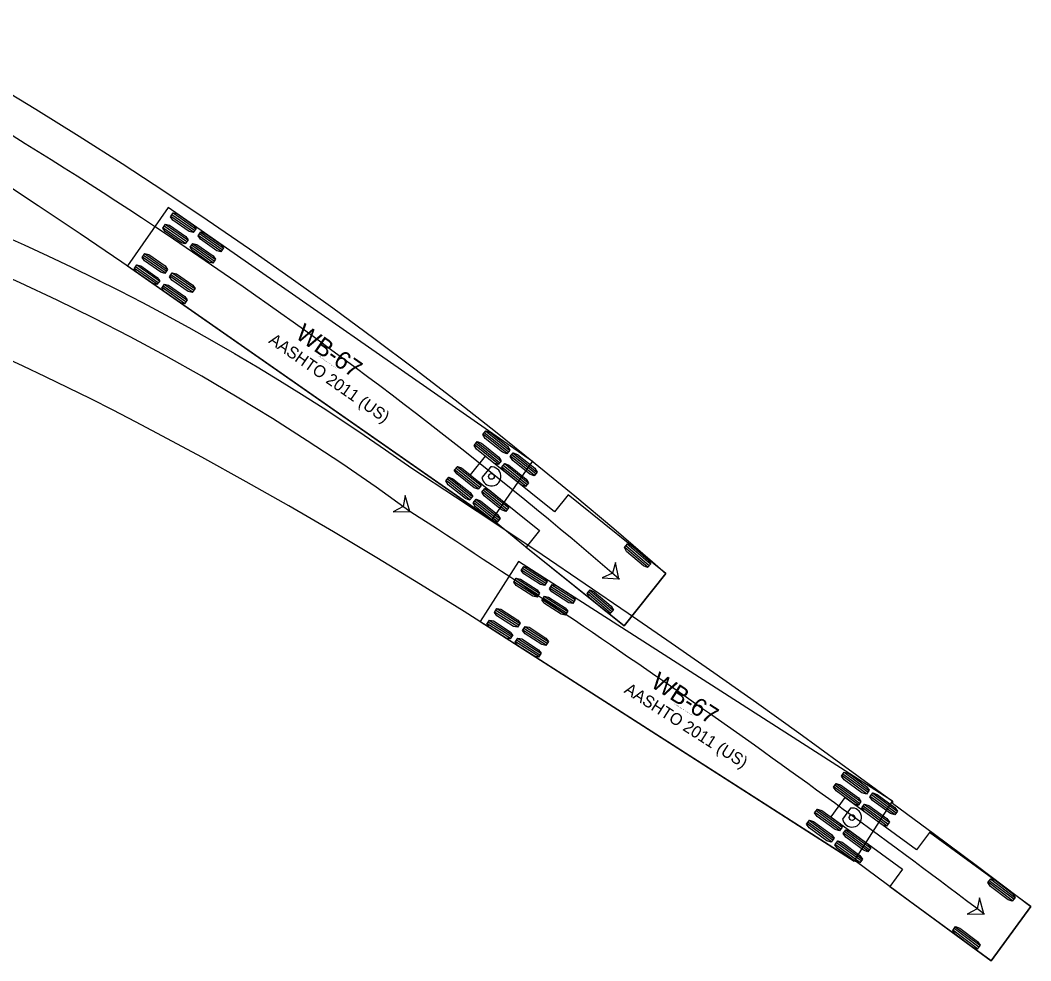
# Model space of a CAD drawing. Extents: x 2175591 to 2194071, y 76570 to 86955.
# Drawn here: x 2176719.9 to 2176840.5, y 77107.8 to 77220.1 of the extents above; entities that cross this region are included whole.
import ezdxf

# ---------------------------------------------------------------- set-up
doc = ezdxf.new("R2010")
doc.units = 0
doc.layers.add('C-UTIL-STRM-TEXT', color=7, linetype='Continuous')

msp = doc.modelspace()

# ---------------------------------------------------------------- linework, layer by layer
at = {"layer": 'C-UTIL-STRM-TEXT'}
for p, q in [((2176737.57, 77197.72), (2176732.71, 77190.75)), ((2176781.04, 77167.4), (2176737.57, 77197.72)), ((2176740.58, 77194.79), (2176737.87, 77196.67)), ((2176740.71, 77194.97), (2176738.01, 77196.86)), ((2176740.84, 77195.16), (2176738.14, 77197.05)), ((2176739.64, 77193.43), (2176736.93, 77195.32)), ((2176739.77, 77193.62), (2176737.06, 77195.51)), ((2176739.9, 77193.81), (2176737.19, 77195.7)), ((2176743.86, 77192.5), (2176741.15, 77194.38)), ((2176743.99, 77192.68), (2176741.29, 77194.57)), ((2176744.12, 77192.87), (2176741.42, 77194.76)), ((2176742.92, 77191.14), (2176740.21, 77193.03)), ((2176743.05, 77191.33), (2176740.34, 77193.22)), ((2176743.18, 77191.52), (2176740.47, 77193.41)), ((2176737.19, 77189.92), (2176734.48, 77191.81)), ((2176737.32, 77190.11), (2176734.61, 77192)), ((2176737.45, 77190.29), (2176734.74, 77192.18)), ((2176732.71, 77190.75), (2176776.17, 77160.43)), ((2176736.24, 77188.57), (2176733.53, 77190.45)), ((2176736.37, 77188.75), (2176733.67, 77190.64)), ((2176736.5, 77188.94), (2176733.8, 77190.83)), ((2176740.47, 77187.63), (2176737.76, 77189.52)), ((2176740.6, 77187.82), (2176737.89, 77189.71)), ((2176740.73, 77188.01), (2176738.02, 77189.89)), ((2176739.52, 77186.28), (2176736.82, 77188.17)), ((2176739.65, 77186.47), (2176736.95, 77188.35)), ((2176739.78, 77186.65), (2176737.08, 77188.54)), ((2176778.01, 77168.38), (2176775.15, 77170.67)), ((2176778.15, 77168.56), (2176775.29, 77170.85)), ((2176778.3, 77168.74), (2176775.44, 77171.03)), ((2176776.98, 77167.09), (2176774.12, 77169.39)), ((2176777.12, 77167.27), (2176774.26, 77169.57)), ((2176777.26, 77167.45), (2176774.4, 77169.74)), ((2176775.4, 77168.06), (2176773.61, 77165.82)), ((2176783.67, 77161.43), (2176775.4, 77168.06)), ((2176781.29, 77165.75), (2176778.43, 77168.04)), ((2176781.43, 77165.93), (2176778.57, 77168.22)), ((2176781.57, 77166.11), (2176778.71, 77168.4)), ((2176774.61, 77164.14), (2176771.75, 77166.44)), ((2176774.75, 77164.32), (2176771.89, 77166.62)), ((2176774.9, 77164.5), (2176772.04, 77166.79)), ((2176776.02, 77166.76), (2176775.01, 77165.5)), ((2176776.17, 77160.43), (2176781.04, 77167.4)), ((2176780.25, 77164.46), (2176777.39, 77166.76)), ((2176780.4, 77164.64), (2176777.54, 77166.94)), ((2176780.54, 77164.82), (2176777.68, 77167.12)), ((2176781.04, 77167.4), (2176781.04, 77167.4)), ((2176773.58, 77162.85), (2176770.72, 77165.15)), ((2176773.72, 77163.03), (2176770.86, 77165.33)), ((2176773.86, 77163.21), (2176771, 77165.51)), ((2176773.61, 77165.82), (2176781.88, 77159.19)), ((2176778.03, 77161.69), (2176775.17, 77163.99)), ((2176778.17, 77161.87), (2176775.31, 77164.16)), ((2176777.14, 77160.58), (2176774.28, 77162.88)), ((2176777.88, 77161.51), (2176775.02, 77163.81)), ((2176785.28, 77163.43), (2176783.67, 77161.43)), ((2176796.97, 77154.04), (2176785.28, 77163.43)), ((2176776.85, 77160.23), (2176773.99, 77162.52)), ((2176776.99, 77160.4), (2176774.14, 77162.7)), ((2176781.88, 77159.19), (2176780.27, 77157.19)), ((2176780.27, 77157.19), (2176791.97, 77147.8)), ((2176794.82, 77154.8), (2176792.04, 77157.2)), ((2176794.97, 77154.98), (2176792.19, 77157.37)), ((2176795.12, 77155.15), (2176792.34, 77157.54)), ((2176779.38, 77155.49), (2176774.79, 77148.33)), ((2176824, 77126.89), (2176779.38, 77155.49)), ((2176782.5, 77152.67), (2176779.72, 77154.45)), ((2176782.63, 77152.86), (2176779.85, 77154.64)), ((2176782.75, 77153.05), (2176779.97, 77154.84)), ((2176781.61, 77151.28), (2176778.83, 77153.06)), ((2176781.74, 77151.47), (2176778.96, 77153.25)), ((2176781.86, 77151.67), (2176779.08, 77153.45)), ((2176791.97, 77147.8), (2176796.97, 77154.04)), ((2176796.97, 77154.04), (2176796.97, 77154.04)), ((2176785.87, 77150.51), (2176783.09, 77152.29)), ((2176785.99, 77150.7), (2176783.22, 77152.48)), ((2176786.12, 77150.9), (2176783.34, 77152.68)), ((2176790.51, 77149.47), (2176787.73, 77151.87)), ((2176790.66, 77149.65), (2176787.88, 77152.04)), ((2176784.98, 77149.12), (2176782.2, 77150.9)), ((2176785.1, 77149.31), (2176782.32, 77151.1)), ((2176785.23, 77149.51), (2176782.45, 77151.29)), ((2176790.36, 77149.3), (2176787.58, 77151.7)), ((2176779.3, 77147.67), (2176776.52, 77149.45)), ((2176779.42, 77147.87), (2176776.65, 77149.65)), ((2176779.55, 77148.06), (2176776.77, 77149.84)), ((2176774.79, 77148.33), (2176819.42, 77119.73)), ((2176778.53, 77146.48), (2176775.76, 77148.26)), ((2176778.66, 77146.67), (2176775.88, 77148.45)), ((2176778.41, 77146.28), (2176775.63, 77148.06)), ((2176782.67, 77145.52), (2176779.89, 77147.3)), ((2176782.79, 77145.71), (2176780.01, 77147.49)), ((2176782.92, 77145.9), (2176780.14, 77147.68)), ((2176781.78, 77144.13), (2176779, 77145.91)), ((2176781.9, 77144.32), (2176779.12, 77146.1)), ((2176782.03, 77144.51), (2176779.25, 77146.29)), ((2176821.19, 77128.13), (2176818.23, 77130.3)), ((2176820.22, 77126.8), (2176817.26, 77128.96)), ((2176820.92, 77127.76), (2176817.96, 77129.93)), ((2176821.06, 77127.95), (2176818.1, 77130.11)), ((2176819.95, 77126.43), (2176816.99, 77128.59)), ((2176820.08, 77126.61), (2176817.12, 77128.78)), ((2176824.58, 77125.65), (2176821.62, 77127.82)), ((2176818.33, 77127.33), (2176816.64, 77125.01)), ((2176826.89, 77121.07), (2176818.33, 77127.33)), ((2176819.42, 77119.73), (2176824, 77126.89)), ((2176824.31, 77125.28), (2176821.35, 77127.45)), ((2176824.45, 77125.47), (2176821.49, 77127.63)), ((2176824, 77126.89), (2176824, 77126.89)), ((2176817.72, 77123.37), (2176814.76, 77125.54)), ((2176817.85, 77123.56), (2176814.89, 77125.72)), ((2176817.99, 77123.74), (2176815.03, 77125.91)), ((2176819.01, 77126.06), (2176818.05, 77124.75)), ((2176823.34, 77123.95), (2176820.38, 77126.12)), ((2176823.47, 77124.14), (2176820.51, 77126.3)), ((2176823.61, 77124.32), (2176820.65, 77126.49)), ((2176816.74, 77122.04), (2176813.78, 77124.21)), ((2176816.88, 77122.23), (2176813.92, 77124.39)), ((2176817.01, 77122.41), (2176814.05, 77124.58)), ((2176816.64, 77125.01), (2176825.2, 77118.76)), ((2176821.11, 77120.9), (2176818.15, 77123.06)), ((2176821.24, 77121.08), (2176818.28, 77123.25)), ((2176821.38, 77121.27), (2176818.42, 77123.43)), ((2176828.41, 77123.15), (2176826.89, 77121.07)), ((2176840.52, 77114.3), (2176828.41, 77123.15)), ((2176820.13, 77119.57), (2176817.17, 77121.73)), ((2176820.27, 77119.75), (2176817.31, 77121.91)), ((2176820.41, 77119.94), (2176817.44, 77122.1)), ((2176825.2, 77118.76), (2176823.69, 77116.69)), ((2176838.35, 77114.99), (2176835.42, 77117.21)), ((2176838.49, 77115.18), (2176835.56, 77117.39)), ((2176838.62, 77115.36), (2176835.7, 77117.57)), ((2176823.69, 77116.69), (2176835.8, 77107.84)), ((2176835.8, 77107.84), (2176840.52, 77114.3)), ((2176840.52, 77114.3), (2176840.52, 77114.3)), ((2176834.16, 77109.28), (2176831.23, 77111.5)), ((2176834.3, 77109.47), (2176831.37, 77111.68)), ((2176834.43, 77109.65), (2176831.51, 77111.86))]:
    msp.add_line(p, q, dxfattribs=at)
for points in [[(2176716.55, 77212.6), (2176721.75, 77209.45), (2176726.92, 77206.23), (2176732.06, 77202.96), (2176737.16, 77199.63), (2176742.22, 77196.24), (2176747.25, 77192.8), (2176752.25, 77189.31), (2176757.2, 77185.76), (2176762.11, 77182.15), (2176766.99, 77178.49), (2176771.82, 77174.78), (2176776.62, 77171.01), (2176781.37, 77167.19), (2176786.08, 77163.32), (2176790.75, 77159.41), (2176795.35, 77155.45), (2176796.97, 77154.04), (2176791.97, 77147.8), (2176780.46, 77157.03), (2176776.4, 77160.37), (2176776.17, 77160.43), (2176736.94, 77187.8), (2176732.01, 77191.22), (2176727.04, 77194.6), (2176722.04, 77197.94), (2176717.01, 77201.24)], [(2176717.48, 77194.53), (2176720.35, 77193.26), (2176723.21, 77191.95), (2176726.05, 77190.6), (2176728.88, 77189.23), (2176731.69, 77187.82), (2176734.48, 77186.38), (2176737.25, 77184.91), (2176740.01, 77183.4), (2176742.75, 77181.87), (2176745.48, 77180.3), (2176748.18, 77178.7), (2176750.84, 77177.09), (2176753.46, 77175.46), (2176756.05, 77173.81), (2176758.4, 77172.28), (2176760.95, 77170.57), (2176763.5, 77168.82), (2176766.63, 77166.62), (2176771.84, 77163.21), (2176777.02, 77159.78), (2176782.19, 77156.32), (2176787.34, 77152.83), (2176792.47, 77149.32), (2176797.59, 77145.79), (2176802.68, 77142.22), (2176807.76, 77138.64), (2176812.82, 77135.02), (2176817.86, 77131.38), (2176824, 77126.89), (2176824.02, 77126.65), (2176829.02, 77122.96), (2176833.99, 77119.24), (2176840.52, 77114.3), (2176835.8, 77107.84), (2176826.05, 77114.96), (2176819.54, 77119.75), (2176819.42, 77119.73), (2176778.07, 77146.23), (2176772.89, 77149.51), (2176767.69, 77152.75), (2176762.47, 77155.93), (2176757.28, 77159.02), (2176751.97, 77162.11), (2176746.88, 77165), (2176741.58, 77167.94), (2176736.29, 77170.77), (2176733.64, 77172.16), (2176730.98, 77173.53), (2176728.31, 77174.88), (2176725.62, 77176.21), (2176722.93, 77177.52), (2176720.23, 77178.8), (2176717.51, 77180.06)]]:
    msp.add_lwpolyline(points, dxfattribs=at)
for points in [[(2176740.88, 77195.21), (2176740.55, 77194.74), (2176740.07, 77194.86), (2176738.12, 77196.22), (2176737.84, 77196.63), (2176738.17, 77197.1), (2176738.65, 77196.97), (2176740.59, 77195.61)], [(2176739.93, 77193.85), (2176739.6, 77193.39), (2176739.13, 77193.51), (2176737.18, 77194.87), (2176736.9, 77195.27), (2176737.22, 77195.74), (2176737.7, 77195.62), (2176739.65, 77194.26)], [(2176744.16, 77192.92), (2176743.83, 77192.45), (2176743.35, 77192.57), (2176741.4, 77193.93), (2176741.12, 77194.34), (2176741.45, 77194.81), (2176741.93, 77194.68), (2176743.88, 77193.32)], [(2176743.21, 77191.57), (2176742.88, 77191.1), (2176742.41, 77191.22), (2176740.46, 77192.58), (2176740.18, 77192.98), (2176740.51, 77193.45), (2176740.98, 77193.33), (2176742.93, 77191.97)], [(2176737.48, 77190.34), (2176737.15, 77189.87), (2176736.68, 77190), (2176734.73, 77191.36), (2176734.45, 77191.76), (2176734.77, 77192.23), (2176735.25, 77192.11), (2176737.2, 77190.75)], [(2176736.54, 77188.99), (2176736.21, 77188.52), (2176735.73, 77188.64), (2176733.78, 77190), (2176733.5, 77190.41), (2176733.83, 77190.88), (2176734.31, 77190.75), (2176736.26, 77189.39)], [(2176740.76, 77188.05), (2176740.43, 77187.58), (2176739.96, 77187.71), (2176738.01, 77189.07), (2176737.73, 77189.47), (2176738.05, 77189.94), (2176738.53, 77189.82), (2176740.48, 77188.46)], [(2176739.82, 77186.7), (2176739.49, 77186.23), (2176739.01, 77186.35), (2176737.06, 77187.71), (2176736.78, 77188.12), (2176737.11, 77188.59), (2176737.59, 77188.46), (2176739.54, 77187.11)], [(2176778.33, 77168.78), (2176777.97, 77168.33), (2176777.47, 77168.52), (2176775.41, 77170.17), (2176775.11, 77170.63), (2176775.47, 77171.08), (2176775.98, 77170.89), (2176778.04, 77169.24)], [(2176777.3, 77167.49), (2176776.94, 77167.05), (2176776.43, 77167.23), (2176774.37, 77168.89), (2176774.08, 77169.34), (2176774.44, 77169.79), (2176774.95, 77169.6), (2176777.01, 77167.95)], [(2176781.61, 77166.15), (2176781.25, 77165.71), (2176780.74, 77165.89), (2176778.68, 77167.54), (2176778.39, 77168), (2176778.75, 77168.45), (2176779.26, 77168.26), (2176781.32, 77166.61)], [(2176774.93, 77164.54), (2176774.57, 77164.1), (2176774.06, 77164.28), (2176772.01, 77165.94), (2176771.71, 77166.39), (2176772.07, 77166.84), (2176772.58, 77166.65), (2176774.64, 77165)], [(2176780.57, 77164.86), (2176780.22, 77164.42), (2176779.71, 77164.61), (2176777.65, 77166.26), (2176777.36, 77166.71), (2176777.72, 77167.16), (2176778.22, 77166.97), (2176780.28, 77165.32)], [(2176773.9, 77163.26), (2176773.54, 77162.81), (2176773.03, 77163), (2176770.97, 77164.65), (2176770.68, 77165.11), (2176771.04, 77165.55), (2176771.55, 77165.36), (2176773.61, 77163.71)], [(2176778.21, 77161.91), (2176777.85, 77161.47), (2176777.34, 77161.65), (2176775.28, 77163.31), (2176774.99, 77163.76), (2176775.35, 77164.21), (2176775.86, 77164.02), (2176777.91, 77162.37)], [(2176766.41, 77161.46), (2176765.85, 77163.38), (2176765.6, 77162.05), (2176764.41, 77161.42)], [(2176777.17, 77160.63), (2176776.82, 77160.18), (2176776.31, 77160.37), (2176774.25, 77162.02), (2176773.96, 77162.48), (2176774.31, 77162.92), (2176774.82, 77162.74), (2176776.88, 77161.08)], [(2176795.16, 77155.19), (2176794.78, 77154.76), (2176794.28, 77154.96), (2176792.28, 77156.69), (2176792.01, 77157.15), (2176792.38, 77157.59), (2176792.88, 77157.38), (2176794.88, 77155.66)], [(2176782.78, 77153.1), (2176782.47, 77152.62), (2176781.99, 77152.73), (2176779.99, 77154.01), (2176779.69, 77154.4), (2176780, 77154.88), (2176780.48, 77154.78), (2176782.48, 77153.5)], [(2176791.35, 77153.42), (2176790.95, 77155.38), (2176790.59, 77154.08), (2176789.35, 77153.54)], [(2176781.89, 77151.71), (2176781.58, 77151.23), (2176781.1, 77151.34), (2176779.1, 77152.62), (2176778.8, 77153.01), (2176779.11, 77153.49), (2176779.59, 77153.39), (2176781.59, 77152.11)], [(2176786.15, 77150.94), (2176785.84, 77150.46), (2176785.36, 77150.57), (2176783.36, 77151.85), (2176783.06, 77152.24), (2176783.37, 77152.72), (2176783.85, 77152.62), (2176785.85, 77151.34)], [(2176790.7, 77149.69), (2176790.32, 77149.26), (2176789.82, 77149.46), (2176787.82, 77151.19), (2176787.55, 77151.65), (2176787.92, 77152.09), (2176788.42, 77151.88), (2176790.42, 77150.15)], [(2176785.26, 77149.56), (2176784.95, 77149.07), (2176784.47, 77149.18), (2176782.47, 77150.46), (2176782.17, 77150.85), (2176782.48, 77151.34), (2176782.96, 77151.23), (2176784.96, 77149.95)], [(2176779.58, 77148.11), (2176779.27, 77147.63), (2176778.79, 77147.73), (2176776.79, 77149.01), (2176776.49, 77149.41), (2176776.8, 77149.89), (2176777.28, 77149.78), (2176779.28, 77148.5)], [(2176778.69, 77146.72), (2176778.38, 77146.24), (2176777.9, 77146.34), (2176775.9, 77147.62), (2176775.6, 77148.02), (2176775.91, 77148.5), (2176776.39, 77148.39), (2176778.39, 77147.11)], [(2176782.95, 77145.95), (2176782.64, 77145.47), (2176782.16, 77145.57), (2176780.16, 77146.85), (2176779.86, 77147.25), (2176780.17, 77147.73), (2176780.65, 77147.63), (2176782.65, 77146.34)], [(2176782.06, 77144.56), (2176781.75, 77144.08), (2176781.27, 77144.18), (2176779.27, 77145.46), (2176778.97, 77145.86), (2176779.28, 77146.34), (2176779.76, 77146.24), (2176781.76, 77144.95)], [(2176821.23, 77128.18), (2176820.89, 77127.72), (2176820.37, 77127.88), (2176818.24, 77129.44), (2176817.93, 77129.88), (2176818.26, 77130.34), (2176818.78, 77130.18), (2176820.91, 77128.62)], [(2176820.25, 77126.85), (2176819.91, 77126.38), (2176819.4, 77126.55), (2176817.27, 77128.1), (2176816.95, 77128.55), (2176817.29, 77129.01), (2176817.81, 77128.85), (2176819.94, 77127.29)], [(2176824.62, 77125.7), (2176824.28, 77125.24), (2176823.76, 77125.4), (2176821.63, 77126.96), (2176821.32, 77127.4), (2176821.66, 77127.86), (2176822.17, 77127.7), (2176824.3, 77126.14)], [(2176823.64, 77124.37), (2176823.31, 77123.91), (2176822.79, 77124.07), (2176820.66, 77125.63), (2176820.35, 77126.07), (2176820.68, 77126.53), (2176821.2, 77126.37), (2176823.33, 77124.81)], [(2176818.02, 77123.79), (2176817.68, 77123.33), (2176817.17, 77123.49), (2176815.03, 77125.05), (2176814.72, 77125.49), (2176815.06, 77125.95), (2176815.58, 77125.79), (2176817.71, 77124.23)], [(2176817.05, 77122.46), (2176816.71, 77122), (2176816.19, 77122.16), (2176814.06, 77123.72), (2176813.75, 77124.16), (2176814.09, 77124.62), (2176814.6, 77124.46), (2176816.73, 77122.9)], [(2176821.41, 77121.31), (2176821.07, 77120.85), (2176820.56, 77121.02), (2176818.43, 77122.57), (2176818.11, 77123.01), (2176818.45, 77123.48), (2176818.97, 77123.31), (2176821.1, 77121.76)], [(2176820.44, 77119.98), (2176820.1, 77119.52), (2176819.58, 77119.68), (2176817.45, 77121.24), (2176817.14, 77121.68), (2176817.48, 77122.14), (2176817.99, 77121.98), (2176820.13, 77120.42)], [(2176838.66, 77115.4), (2176838.31, 77114.95), (2176837.8, 77115.12), (2176835.7, 77116.71), (2176835.39, 77117.16), (2176835.74, 77117.62), (2176836.25, 77117.45), (2176838.35, 77115.85)], [(2176834.93, 77113.43), (2176834.4, 77115.36), (2176834.13, 77114.03), (2176832.93, 77113.42)], [(2176834.47, 77109.69), (2176834.12, 77109.24), (2176833.61, 77109.41), (2176831.5, 77111), (2176831.2, 77111.45), (2176831.54, 77111.91), (2176832.06, 77111.73), (2176834.16, 77110.14)]]:
    msp.add_lwpolyline(points, close=True, dxfattribs=at)
for centre, radius in [((2176776.14, 77165.63), 0.34), ((2176766.41, 77161.46), 0.0417), ((2176766.41, 77161.46), 0.0417), ((2176791.35, 77153.42), 0.0417), ((2176819.18, 77124.93), 0.34), ((2176834.93, 77113.43), 0.0417)]:
    msp.add_circle(centre, radius, dxfattribs=at)
for centre, radius, start, end in [((2176430.53, 76735.3), 552.28, 49.2072, 61.3738), ((2176608.17, 76944.87), 268.23, 53.8493, 119.9853), ((2176776.14, 77165.63), 1.14, 186.2479, 96.2479), ((2176147.15, 76205.22), 1139.25, 52.86363, 57.07309), ((2176819.18, 77124.93), 1.14, 188.8527, 98.8527)]:
    msp.add_arc(centre, radius, start, end, dxfattribs=at)

# ---------------------------------------------------------------- texts
for s, height, rotation, p in [('WB-67', 2.125, 325.0964, (2176752.61, 77182.25)), ('AASHTO 2011 (US)', 1.4167, 325.0964, (2176749.45, 77181.65)), ('(c) 2019 Transoft Solutions, Inc. All rights reserved.', 0.085, 325.0964, (2176755.43, 77180.03)), ('WB-67', 2.125, 327.3454, (2176795.02, 77140.62)), ('AASHTO 2011 (US)', 1.4167, 327.3454, (2176791.88, 77139.9)), ('(c) 2019 Transoft Solutions, Inc. All rights reserved.', 0.085, 327.3454, (2176797.92, 77138.51))]:
    msp.add_text(s, height=height, rotation=rotation, dxfattribs=at).set_placement(p)

doc.saveas('drawing.dxf')
